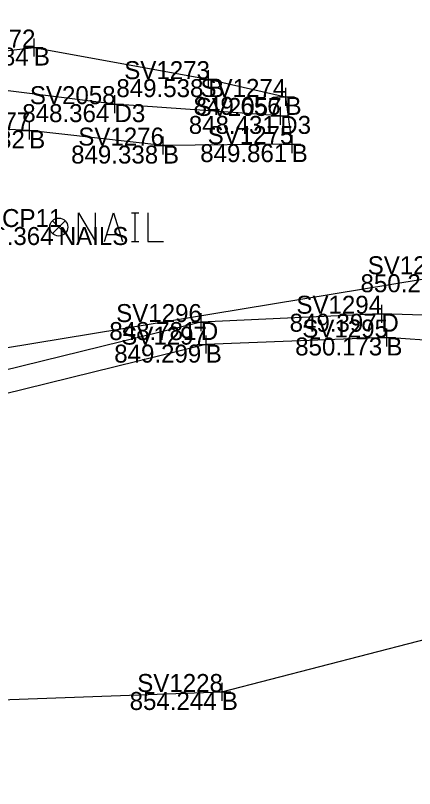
# Model space of a CAD drawing. Extents: x 2125299 to 2129212, y 713100 to 714300.
# Drawn here: x 2128300.4 to 2128322.56, y 714148.53 to 714191.52 of the extents above; entities that cross this region are included whole.
import ezdxf

# ---------------------------------------------------------------- set-up
doc = ezdxf.new("R2010")
doc.units = 0
for name, color, linetype in [('DR_X_Ditch', 7, 'Continuous'), ('RW_P_Esmt_TMP', 7, 'Continuous'), ('RW_X_Esmt_CH', 7, 'Continuous'), ('RW_X_Fee_WL', 7, 'Continuous'), ('SV_X_Break_Lines', 7, 'Continuous'), ('SV_X_Mon_Cells_Found', 7, 'Continuous'), ('SV_X_Text_Name', 7, 'Continuous')]:
    doc.layers.add(name, color=color, linetype=linetype)

msp = doc.modelspace()

# ---------------------------------------------------------------- linework, layer by layer
at = {"layer": 'DR_X_Ditch'}
for points in [[(2128315.102, 714185.935), (2128305.895, 714186.59), (2128297.467, 714187.651), (2128291.656, 714186.324)], [(2128404.428, 714186.272), (2128369.06, 714182.378), (2128353.253, 714176.31), (2128345.761, 714173.482), (2128342.574, 714173.517), (2128335.146, 714174.466), (2128320.718, 714174.933), (2128310.69, 714174.47), (2128298.547, 714171.487), (2128292.157, 714172.437), (2128287.299, 714171.899), (2128282.282, 714171.907)]]:
    msp.add_lwpolyline(points, dxfattribs=at)
at = {"layer": 'SV_X_Break_Lines'}
for points in [[(2128294.731, 714221.25), (2128286.429, 714216.107), (2128286.307, 714216.085), (2128290.211, 714206.434), (2128289.886, 714198.061), (2128291.79, 714193.305), (2128293.753, 714188.829), (2128301.414, 714189.738), (2128311.099, 714187.98), (2128315.392, 714186.993), (2128315.738, 714184.367), (2128308.586, 714184.286), (2128301.154, 714185.129), (2128295.038, 714185.419), (2128293.414, 714179.277), (2128290.994, 714176.583), (2128286.414, 714175.49), (2128286.417, 714175.493), (2128286.617, 714173.173), (2128291.92, 714175.499), (2128298.034, 714172.742), (2128324.661, 714177.129), (2128340.162, 714175.773), (2128345.323, 714175.683)], [(2128257.59, 714155.557), (2128263.487, 714153.243), (2128269.265, 714148.527), (2128290.131, 714150.799), (2128296.994, 714153.375), (2128311.857, 714153.897), (2128347.24, 714163.065), (2128380.908, 714169.426), (2128405.403, 714183.348)], [(2128342.539, 714171.803), (2128334.728, 714172.648), (2128320.995, 714173.612), (2128310.963, 714173.215), (2128298.394, 714170.12), (2128293.384, 714169.367), (2128288.065, 714167.811), (2128285.175, 714167.243), (2128284.357, 714164.829), (2128284.794, 714163.766)]]:
    msp.add_lwpolyline(points, dxfattribs=at)
at = {"layer": 'SV_X_Mon_Cells_Found'}
for p, q in [((2128301.414, 714190.238), (2128301.414, 714189.238)), ((2128300.914, 714189.738), (2128301.914, 714189.738)), ((2128301.414, 714189.738), (2128301.414, 714189.738)), ((2128311.099, 714188.48), (2128311.099, 714187.48)), ((2128310.599, 714187.98), (2128311.599, 714187.98)), ((2128311.099, 714187.98), (2128311.099, 714187.98)), ((2128315.392, 714187.493), (2128315.392, 714186.493)), ((2128305.895, 714187.09), (2128305.895, 714186.09)), ((2128314.892, 714186.993), (2128315.892, 714186.993)), ((2128315.392, 714186.993), (2128315.392, 714186.993)), ((2128305.395, 714186.59), (2128306.395, 714186.59)), ((2128305.895, 714186.59), (2128305.895, 714186.59)), ((2128315.102, 714186.435), (2128315.102, 714185.435)), ((2128314.602, 714185.935), (2128315.602, 714185.935)), ((2128315.102, 714185.935), (2128315.102, 714185.935)), ((2128301.154, 714185.629), (2128301.154, 714184.629)), ((2128300.654, 714185.129), (2128301.654, 714185.129)), ((2128301.154, 714185.129), (2128301.154, 714185.129)), ((2128308.586, 714184.786), (2128308.586, 714183.786)), ((2128315.738, 714184.867), (2128315.738, 714183.867)), ((2128308.086, 714184.286), (2128309.086, 714184.286)), ((2128308.586, 714184.286), (2128308.586, 714184.286)), ((2128315.238, 714184.367), (2128316.238, 714184.367)), ((2128315.738, 714184.367), (2128315.738, 714184.367)), ((2128320.718, 714175.433), (2128320.718, 714174.433)), ((2128310.69, 714174.97), (2128310.69, 714173.97)), ((2128320.218, 714174.933), (2128321.218, 714174.933)), ((2128320.718, 714174.933), (2128320.718, 714174.933)), ((2128310.19, 714174.47), (2128311.19, 714174.47)), ((2128310.69, 714174.47), (2128310.69, 714174.47)), ((2128320.995, 714174.112), (2128320.995, 714173.112)), ((2128310.963, 714173.715), (2128310.963, 714172.715)), ((2128320.495, 714173.612), (2128321.495, 714173.612)), ((2128320.995, 714173.612), (2128320.995, 714173.612)), ((2128310.463, 714173.215), (2128311.463, 714173.215)), ((2128310.963, 714173.215), (2128310.963, 714173.215)), ((2128311.857, 714154.397), (2128311.857, 714153.397)), ((2128311.357, 714153.897), (2128312.357, 714153.897)), ((2128311.857, 714153.897), (2128311.857, 714153.897))]:
    msp.add_line(p, q, dxfattribs=at)
at = {"layer": 'SV_X_Text_Name'}
for p, q in [((2128302.444, 714180.109), (2128303.152, 714179.402)), ((2128302.444, 714179.402), (2128303.152, 714180.109))]:
    msp.add_line(p, q, dxfattribs=at)
for points in [[(2128303.888, 714178.946), (2128303.888, 714180.546), (2128304.832, 714178.946), (2128304.832, 714180.546)], [(2128305.336, 714178.946), (2128305.84, 714180.546), (2128306.331, 714178.946)], [(2128306.835, 714180.546), (2128307.238, 714180.546)], [(2128307.037, 714178.946), (2128307.037, 714180.546)], [(2128307.742, 714180.546), (2128307.742, 714178.946), (2128308.612, 714178.946)], [(2128306.205, 714179.324), (2128305.462, 714179.324)], [(2128306.835, 714178.946), (2128307.238, 714178.946)]]:
    msp.add_lwpolyline(points, dxfattribs=at)
msp.add_circle((2128302.798, 714179.755), 0.5, dxfattribs=at)

# ---------------------------------------------------------------- texts
at = {"layer": 'RW_P_Esmt_TMP'}
for s, p in [('B', (2128301.414, 714188.738)), ('B', (2128311.099, 714186.98)), ('B', (2128315.392, 714185.993)), ('D3', (2128305.895, 714185.59)), ('D3', (2128315.102, 714184.935)), ('B', (2128301.154, 714184.129)), ('B', (2128308.586, 714183.286)), ('B', (2128315.738, 714183.367)), ('NAILS', (2128302.798, 714178.755)), ('D', (2128320.718, 714173.933)), ('D', (2128310.69, 714173.47)), ('B', (2128320.995, 714172.612)), ('B', (2128310.963, 714172.215)), ('B', (2128311.857, 714152.897))]:
    msp.add_text(s, height=1, dxfattribs=at).set_placement(p)
at = {"layer": 'RW_X_Esmt_CH'}
for s, p in [('SV1272', (2128296.743, 714189.738)), ('SV1273', (2128306.437, 714187.98)), ('SV1274', (2128310.672, 714186.993)), ('SV2058', (2128301.196, 714186.59)), ('SV2057', (2128310.408, 714185.935)), ('SV1277', (2128296.46, 714185.129)), ('SV1275', (2128311.069, 714184.367)), ('SV1276', (2128303.884, 714184.286)), ('CP11', (2128299.651, 714179.755)), ('SV1286', (2128319.959, 714177.129)), ('SV1294', (2128315.998, 714174.933)), ('SV1296', (2128305.988, 714174.47)), ('SV1295', (2128316.326, 714173.612)), ('SV1297', (2128306.269, 714173.215)), ('SV1228', (2128307.158, 714153.897))]:
    msp.add_text(s, height=1, dxfattribs=at).set_placement(p)
at = {"layer": 'RW_X_Fee_WL'}
for s, p in [('848.684', (2128296.292, 714188.738)), ('849.538', (2128305.999, 714186.98)), ('849.656', (2128310.288, 714185.993)), ('848.364', (2128300.773, 714185.59)), ('848.431', (2128310.02, 714184.935)), ('848.782', (2128296.081, 714184.129)), ('849.338', (2128303.486, 714183.286)), ('849.861', (2128310.656, 714183.367)), ('849.364', (2128297.676, 714178.755)), ('850.298', (2128319.561, 714176.129)), ('849.397', (2128315.622, 714173.933)), ('848.781', (2128305.608, 714173.47)), ('850.173', (2128315.931, 714172.612)), ('849.299', (2128305.879, 714172.215)), ('854.244', (2128306.735, 714152.897))]:
    msp.add_text(s, height=1, dxfattribs=at).set_placement(p)

doc.saveas('drawing.dxf')
